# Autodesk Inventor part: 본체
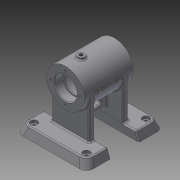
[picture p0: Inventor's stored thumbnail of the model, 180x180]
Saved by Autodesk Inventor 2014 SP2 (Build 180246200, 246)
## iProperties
Created: 2016-07
Part Number: 본체
Material: Generic
Document SubType Name: Modeling
Designer: 거성
Density: 1 g/cm^3
Appearance: Default
Author: 거성
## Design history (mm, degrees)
sketch "스케치1"
  geometry: C1 r 27 at (0, 0); 1 further point
  constraints: 1 centre point, 1 coincident
  dimensions: "d0" = 54 diameter of C1
extrude "돌출1" new body sketch "스케치1" distance "d1" = 70; taper "d2" = 0 deg
sketch "스케치2"
  geometry: C1 r 27 at (0, 0) reference; C2 r 16 at (0, 0)
  constraints: 1 centre point, 1 coincident
  dimensions: "d3" = 16 radius of C2
extrude "돌출2" cut sketch "스케치2" distance "d4" = 12; taper "d5" = 0 deg
sketch "스케치5"
  geometry: C1 r 16 at (0, 0) reference; C2 r 14 at (0, 0)
  constraints: 1 centre point, 1 coincident
  dimensions: "d12" = 14 radius of C2
extrude "돌출5" cut sketch "스케치5" distance "d13" = 2; taper "d14" = 0 deg
sketch "스케치6"
  geometry: C1 r 14 at (0, 0) reference; C2 r 22 at (0, 0)
  constraints: 1 centre point, 1 coincident
  dimensions: "d15" = 22 radius of C2
extrude "돌출6" cut sketch "스케치6" distance "d16" = 42; taper "d17" = 0 deg
sketch "스케치7"
  geometry: C1 r 27 at (0, 0) reference; C2 r 16 at (0, 0)
  constraints: 1 centre point, 1 coincident
  dimensions: "d18" = 16 radius of C2
extrude "돌출7" cut sketch "스케치7" distance "d19" = 12; taper "d20" = 0 deg
sketch "스케치8"
  geometry: C1 r 16 at (0, 0) reference; C2 r 14 at (0, 0)
  constraints: 1 centre point, 1 coincident
  dimensions: "d21" = 14 radius of C2
extrude "돌출8" cut sketch "스케치8" distance "d22" = 2; taper "d23" = 0 deg
node "작업 평면1"
node "작업 평면2"
sketch "스케치10"
  geometry: L1 (-58, 20)-(-58, -15) reference; L2 (-58, -90)-(-58, -55) reference; L3 (-70, -90)-(-58, -90) reference; L4 (-70, -55)-(-58, -55) reference; L5 (-70, -15)-(-58, -15) reference; L6 (-70, 20)-(-58, 20) reference; L7 (-27, 0)-(-27, -70) reference; L8 (-70, -90)-(-58, -85.632); L9 (-70, -55)-(-70, -90) reference; L10 (-70, 20)-(-58, 15.632); L11 (-70, 20)-(-70, -15) reference; 1 further point
  constraints: 4 end point, 2 point on line
  dimensions: "d34" = 110 deg angle of L9 L8; "d35" = 110 deg angle of L11 L10
extrude "돌출10" cut sketch "스케치10" stored distance "d36" = 12; taper "d37" = 0 deg
node "작업 평면3"
sketch "스케치12"
  geometry: L1 (100, 12)-(0, 12) reference; L2 (23, 70)-(23, 12); L3 (77, 70)-(77, 12); L4 (23, 12)-(77, 12); C1 r 22 at (50, 70) reference; A1 r 27 centre (50, 70) between (23, 70) and (77, 70) reference; 1 further point
  constraints: 6 end point, 2 perpendicular, 2 point on circle, 2 point on line, 1 collinear
  dimensions: "d39" = 54 distance between parallel lines of L3 L2; "d40" = 27 distance from line of point (50, 70) L2
feature "리브1" sketch "스케치12" dims "d41" = 1, "d42" = 8, "d43" = 0, "d44" = 0, "d45" = 1, "d46" = 1
node "작업 평면4"
node "작업 평면5"
sketch "스케치13"
  geometry: L1 (-58, -15)-(0, -15) reference; L2 (-27, 0)-(-27, -70) reference; L3 (-58, -55)-(0, -55) reference; L4 (-70, 20)-(-70, -15) reference; L5 (-70, -55)-(-70, -90) reference; L6 (-48, -15)-(-48, -55); L7 (-38, -27)-(-38, -43); L8 (-34.5, -27)-(-34.5, -43); L9 (-41.5, -43)-(-41.5, -27); L10 (-38, -23.5)-(-38, -46.5); L11 (-48, -35)-(-67.559, -35); L12 (-48, -15)-(-22, -15); L13 (-22, -55)-(-48, -55); L14 (-22, -14)-(-22, -56) reference; L15 (-22, -55)-(-22, -15); A1 r 3.5 centre (-38, -27) between (-34.5, -27) and (-41.5, -27); A2 r 3.5 centre (-38, -43) between (-41.5, -43) and (-34.5, -43); 3 further points
  constraints: 20 end point, 6 point on circle, 4 point on line, 4 tangent, 3 midpoint, 3 parallel, 2 centre point, 2 collinear, 1 horizontal alignment, 1 perpendicular
  dimensions: "d48" = 21 distance between parallel lines of L2 L6; "d49" = 32 distance between parallel lines of L5 L7; "d50" = 23 distance of L10.start L10.end; "d51" = 3.5 radius of A2
extrude "돌출11" join sketch "스케치13" stored distance "d53" = 8; taper "d54" = 0 deg
sketch "스케치14" dims "d55" = 42
  geometry: C1 r 27 at (0, 0) reference; 2 further points
  constraints: 1 coincident, 1 vertical alignment, 2 other
hole "구멍1" sketch "스케치14" at (0, 21) diameter "d56" = 3.242; stored, may be unused: countersink angle "d60" = 90 deg, drill point angle "d62" = 118 deg; dims "d57" = 8, "d58" = 4, "d59" = 2, "d61" = 10
node "작업 평면6"
sketch "스케치15"
  geometry: L1 (0, 0)-(15.898, -25.441); L2 (0, 0)-(0, -27); 1 further point
  constraints: 4 end point, 1 vertical, 1 vertical alignment, 1 other
  dimensions: "d66" = 32 deg angle of L1 L2; "d67" = 30 distance of L1.start L1.end
node "작업 평면7"
node "작업 평면8"
node "작업 평면9"
sketch "스케치18"
  geometry: L1 (-48, -15)-(-48, -55) reference; L2 (27, 0)-(27, -70) reference; 3 further points
  constraints: 1 horizontal alignment, 1 midpoint, 1 other
  dimensions: "d99" = 27 distance from line of point (0, -35) L2
feature "엠보싱1" sketch "스케치18" dims "d100" = 0.5, "d101" = 0
node "작업 평면10"
sketch "스케치19"
  geometry: L1 (0, 0)-(0, -27); L2 (0, 0)-(-15.898, -25.441); C1 r 1.621 at (-21, 0) reference; C2 r 1.621 at (0, -21) reference; C3 r 1.621 at (21, 0) reference; C4 r 1.621 at (0, 21) reference; C5 r 16 at (0, 0) reference; 1 further point
  constraints: 4 end point, 1 vertical, 1 vertical alignment, 1 other
  dimensions: "d102" = 32 deg angle of L1 L2; "d103" = 30 distance of L1.start L2.end
  node "투영된 루프1"
node "작업 평면11"
sketch "스케치20"
  geometry: C1 r 6 at (0, 0); 1 further point
  constraints: 1 centre point
  dimensions: "d104" = 6 radius of C1
extrude "돌출14" join sketch "스케치20" stored distance "d105" = 8; taper "d106" = 0 deg
hole "구멍4" diameter "d109" = 5.188; stored, may be unused: countersink angle "d113" = 90 deg, drill point angle "d115" = 118 deg; dims "d107" = 10, "d108" = 10, "d110" = 15, "d111" = 4, "d112" = 2, "d114" = 10
fillet "모깎기1" dims "d116" = 0.3
fillet "모깎기2" dims "d117" = 3
fillet "모깎기3" dims "d118" = 2
fillet "모깎기4" dims "d119" = 2
chamfer "모따기1" distance "d124" = 1; stored, may be unused: second distance "d125" = 2, angle "d126" = 45 deg
node "작업 평면12"
sketch "스케치21"
  geometry: L1 (-25.063, 27.017)-(74.937, 27.017); L2 (74.937, 27.017)-(74.937, -7.983); L3 (74.937, -7.983)-(-25.063, -7.983); L4 (-25.063, -7.983)-(-25.063, 27.017); L5 (47, -10)-(47, -46) reference; L6 (48.276, 2)-(1.724, 2) reference; L7 (52, -2)-(52, -6) reference; L8 (30.586, -10)-(48.276, -10) reference; L9 (30.586, -46)-(30.586, -10) reference; L10 (48.276, -46)-(30.586, -46) reference; L11 (52, -50)-(52, -54) reference; L12 (1.724, -58)-(48.276, -58) reference; L13 (-2, -50)-(-2, -54) reference; L14 (19.414, -46)-(1.724, -46) reference; L15 (19.414, -10)-(19.414, -46) reference; L16 (1.724, -10)-(19.414, -10) reference; L17 (-2, -2)-(-2, -6) reference; L18 (51.915, -42.566)-(51.915, -45.463) reference; L19 (51.915, -45.463)-(51.942, -45.463) reference; L20 (51.942, -45.463)-(51.942, -43.014) reference; L21 (51.942, -43.014)-(51.993, -43.014) reference; L22 (51.993, -43.014)-(51.993, -45.198) reference; L23 (51.993, -45.198)-(51.999, -45.198) reference; L24 (51.999, -45.198)-(51.999, -43.014) reference; L25 (51.999, -43.014)-(51.978, -43.014) reference; L26 (51.959, -42.566)-(51.915, -42.566) reference; L27 (51.966, -37.803)-(51.966, -38.834) reference; L28 (51.966, -38.834)-(51.85, -38.834) reference; L29 (51.85, -38.834)-(51.85, -39.208) reference; L30 (51.874, -39.289)-(51.963, -39.289) reference; L31 (51.963, -39.289)-(51.963, -38.834) reference; L32 (51.963, -38.834)-(51.981, -38.834) reference; L33 (51.981, -38.834)-(51.981, -37.803) reference; L34 (51.981, -37.803)-(51.966, -37.803) reference; L35 (51.869, -36.67)-(51.869, -37.071) reference; L36 (51.873, -27.512)-(51.928, -27.512) reference; L37 (51.928, -27.512)-(51.928, -25.958) reference; L38 (51.928, -25.958)-(51.895, -25.958) reference; L39 (51.895, -25.958)-(51.895, -29.526) reference; L40 (51.895, -29.526)-(51.928, -29.526) reference; L41 (51.928, -29.526)-(51.928, -27.966) reference; L42 (51.928, -27.966)-(51.873, -27.966) reference; L43 (51.873, -27.966)-(51.873, -27.512) reference; L44 (51.895, -23.122)-(51.895, -23.665) reference; L45 (51.873, -25.564)-(51.873, -25.083) reference; L46 (51.978, -24.526)-(51.978, -22.274) reference; L47 (51.873, -21.704)-(51.873, -21.223) reference; L48 (51.857, -9.147)-(51.857, -10.626) reference; L49 (51.857, -10.626)-(51.891, -10.626) reference; L50 (51.891, -10.626)-(51.891, -9.147) reference; L51 (51.891, -9.147)-(51.857, -9.147) reference; L52 (51.861, -12.939)-(51.992, -12.939) reference; L53 (51.992, -12.939)-(51.992, -14.058) reference; L54 (51.992, -14.058)-(51.999, -14.058) reference; L55 (51.999, -14.058)-(51.999, -12.939) reference; L56 (51.999, -12.939)-(51.959, -12.939) reference; L57 (51.959, -12.939)-(51.959, -12.464) reference; L58 (51.959, -12.464)-(51.833, -12.464) reference; L59 (51.833, -12.464)-(51.833, -12.769) reference; L60 (51.963, -9.269)-(51.89, -9.269) reference; L61 (51.89, -9.269)-(51.89, -13.156) reference; L62 (51.89, -13.156)-(51.853, -13.156) reference; L63 (51.853, -13.156)-(51.853, -8.807) reference; L64 (51.853, -8.807)-(51.974, -8.807) reference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; 65 further points; 1 other entity
  constraints: 10 end point, 2 midpoint, 2 parallel, 1 horizontal, 1 perpendicular, 1 vertical alignment, 86 other
  dimensions: "d128" = 35 distance of L1.end L2.end; "d129" = 100 distance of L1.start L1.end; "d130" = 55 distance of point (24.937, -27.983) point (24.937, 27.017)
extrude "돌출15" join sketch "스케치21" distance "d131" = 12; taper "d132" = 0 deg
sketch "스케치22"
  geometry: L1 (0, 0)-(35, 0) reference; L2 (0, 0)-(0, -12) reference; L3 (35, -12)-(0, -12) reference; L4 (0, -12)-(4.368, 0); 1 further point
  constraints: 2 end point, 1 point on line
  dimensions: "d133" = 110 deg angle of L3 L4
sketch "스케치23"
  geometry: L1 (0, 0)-(100, 0) reference; L2 (100, -12)-(0, -12) reference; L3 (100, 0)-(100, -12) reference; L4 (100, -12)-(95.632, 0); 1 further point
  constraints: 2 end point, 1 point on line
  dimensions: "d134" = 110 deg angle of L2 L4
extrude "돌출16" cut sketch "스케치22" stored distance "d135" = 12; taper "d136" = 0 deg
extrude "돌출17" cut sketch "스케치23" stored distance "d137" = 12; taper "d138" = 0 deg
node "작업 평면13"
node "작업 평면14"
fillet "모깎기9" dims "d140" = 10
fillet "모깎기10" dims "d141" = 2
fillet "모깎기11" dims "d178" = 2
node "작업 평면15"
sketch "스케치24"
  geometry: L1 (-2, 7)-(52, 7) reference; L2 (25, 7)-(25, -15); C1 r 5 at (25, -15)
  constraints: 2 end point, 1 centre point, 1 coincident, 1 perpendicular
  dimensions: "d180" = 22 distance of L2.start L2.end; "d181" = 10 diameter of C1
extrude "돌출18" join sketch "스케치24" stored distance "d182" = 12; taper "d183" = 0 deg
hole "구멍9" diameter "d186" = 5.188; stored, may be unused: countersink angle "d190" = 90 deg, drill point angle "d192" = 118 deg; dims "d184" = 10, "d185" = 10, "d187" = 15, "d188" = 10, "d189" = 4, "d191" = 10
fillet "모깎기12" dims "d193" = 2
sketch "스케치25"
  geometry: L1 (61.651, -21.249)-(-11.778, -21.249) reference; L2 (-25.063, -17.62)-(-25.063, 5.983) reference; L3 (65.54, -27.017)-(-15.666, -27.017) reference; L4 (24.937, -27.017)-(24.937, -14.517); L5 (-11.778, -21.249)-(61.651, -21.249); 4 further points
  constraints: 4 end point, 3 symmetric about line, 1 midpoint, 1 perpendicular
  dimensions: "d197" = 12.5 distance from line of point (-12.563, -14.517) L2; "d198" = 12.5 distance from line of point (-12.563, -14.517) L3
hole "구멍10" sketch "스케치25" at (-12.563, -14.517), (48.335, -61.324), (62.437, -14.517) diameter "d199" = 6; stored, may be unused: countersink angle "d203" = 90 deg, drill point angle "d205" = 118 deg; dims "d200" = 15, "d201" = 10, "d202" = 4, "d204" = 10
node "작업 평면16"
fillet "모깎기13" dims "d206" = 2
node "솔리드1"
mirror "대칭1"
pattern_circular "원형 패턴1" dims angle "d64" = 360 deg
mirror "대칭2"
mirror "대칭3"
mirror "대칭4"
mirror "대칭5"
mirror "대칭6"
node "투영된 루프2"
other parameters: "d33" = 0, "d47" = 0, "d98" = 27, "d127" = 0
